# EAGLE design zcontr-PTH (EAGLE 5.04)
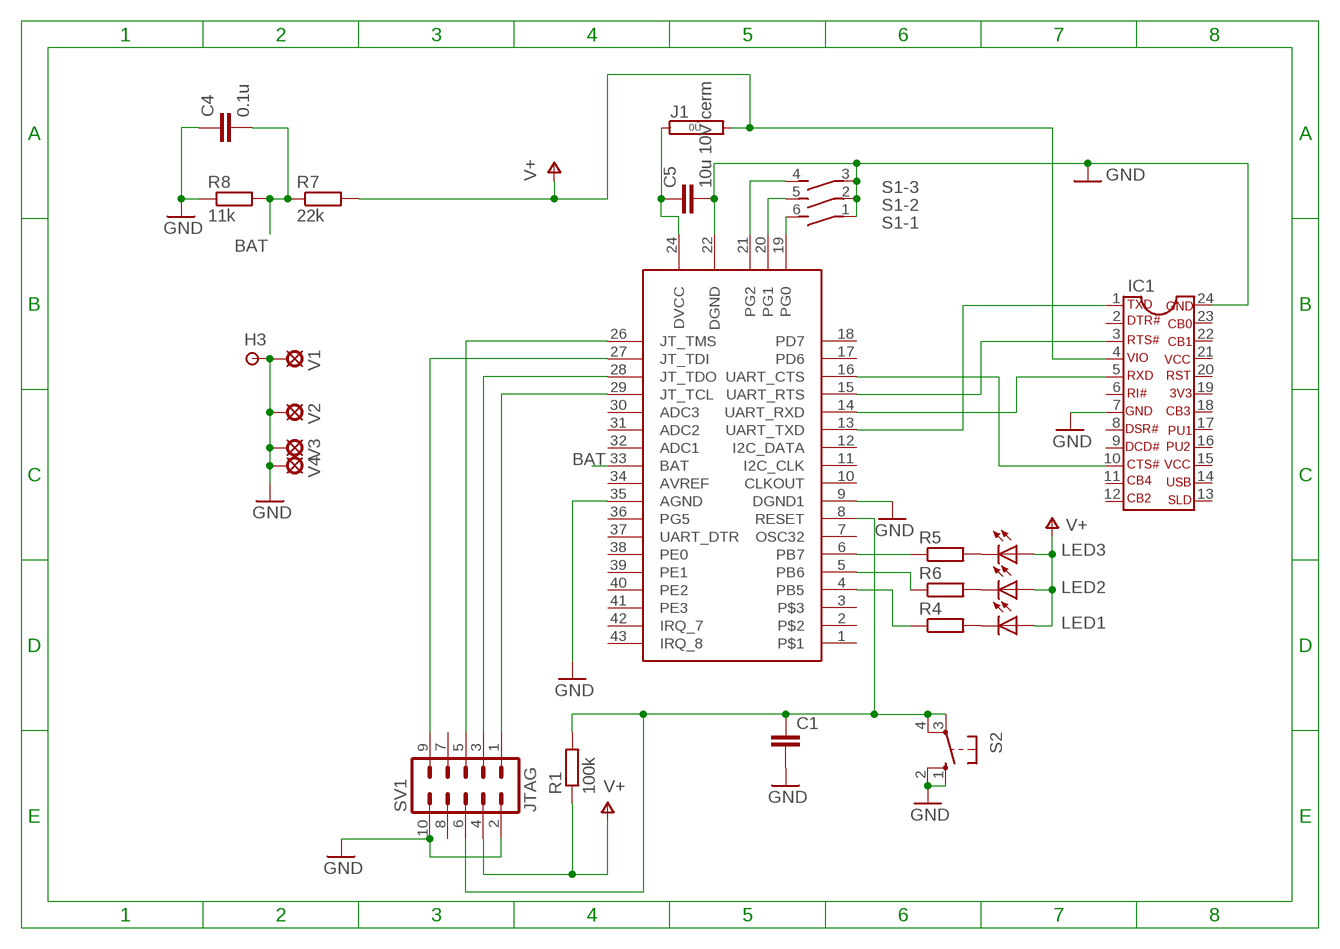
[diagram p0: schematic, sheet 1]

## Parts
C1  C2.5P  [C025-030X050]
C4  0.1u  C5P  [C050-030-075]
C5  10u 10V cerm  CSMT0805  [C0805]
H3  HOLE/SMALL  [1,6/0,8]
IC1  UM232R-6  [DIL24-6]
J1  0R  [0R/10]
LED1  LED-3MM3MM  [HLMP-D105]
LED2  LED-3MM3MM  [HLMP-D105]
LED3  LED-3MM3MM  [HLMP-D105]
R1  100k  R  [0207/10]
R4  470  R  [0207/10]
R5  150  R  [0207/10]
R6  220  R  [0207/10]
R7  22k  R  [0207/10]
R8  11k  R  [0207/10]
S1  DIP-SW-03  [DIP-SW-3]
S2  10-XX  [B3F-10XX]
SV1  JTAG  ML10  [ML10]
U$1  ZDM-A1281-A2N  [ZIGSMD]
V1  HOLE/VIA  [LSP10]
V2  HOLE/VIA  [LSP10]
V3  HOLE/VIA  [LSP10]
V4  HOLE/VIA  [LSP10]

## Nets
BAT: C4.2 R7.1 R8.2 U$1.33(BAT)
GND [supply]: C1.2 C4.1 C5.2 H3.1(P) IC1.7 IC1.24 R8.1 S1.1 S1.2 S1.3 S2.1(S) S2.2(S1) SV1.2 SV1.10 U$1.9(DGND1) U$1.22(DGND) U$1.35(AGND) V1.MP V2.MP V3.MP V4.MP
N$1: S1.6 U$1.19(PG0)
N$2: IC1.10 U$1.16(UART_CTS)
N$3: IC1.3 U$1.15(UART_RTS)
N$4: IC1.5 U$1.14(UART_RXD)
N$5: IC1.1 U$1.13(UART_TXD)
N$6: LED3.K(C) R5.2
N$7: LED2.K(C) R6.2
N$8: LED1.K(C) R4.2
N$9: R5.1 U$1.6(PB7)
N$10: SV1.1 U$1.29(JT_TCL)
N$11: SV1.9 U$1.27(JT_TDI)
N$12: SV1.3 U$1.28(JT_TDO)
N$13: C1.1 R1.2 S2.3(P) S2.4(P1) SV1.6 U$1.8(RESET)
N$14: R6.1 U$1.5(PB6)
N$15: R4.1 U$1.4(PB5)
N$16: S1.5 U$1.20(PG1)
N$17: S1.4 U$1.21(PG2)
N$19: SV1.5 U$1.26(JT_TMS)
N$31 [supply]: C5.1 J1.1 U$1.24(DVCC)
V+: IC1.4 J1.2 LED1.A LED2.A LED3.A R1.1 R7.2 SV1.4
Unconnected: IC1.2 IC1.6 IC1.8 IC1.9 IC1.11 IC1.12 IC1.13 IC1.14 IC1.15 IC1.16 IC1.17 IC1.18 IC1.19 IC1.20 IC1.21 IC1.22 IC1.23 SV1.7 SV1.8 U$1.1 U$1.2 U$1.3 U$1.7(OSC32) U$1.10(CLKOUT) U$1.11(I2C_CLK) U$1.12(I2C_DATA) U$1.17(PD6) U$1.18(PD7) U$1.30(ADC3) U$1.31(ADC2) U$1.32(ADC1) U$1.34(AVREF) U$1.36(PG5) U$1.37(UART_DTR) U$1.38(PE0) U$1.39(PE1) U$1.40(PE2) U$1.41(PE3) U$1.42(IRQ_7) U$1.43(IRQ_8)

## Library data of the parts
C1 C4 C5 = ee2parts:C: Capacitor
H3 = ee2parts:HOLE/SMALL: SMALL THROUGH-HOLE PAD/TESTPOINT
IC1 = ee2parts:UM232R: USB to Serial Module Provides easy USB interface to serial (UART) with power supply
J1 = jumper:0R: Bridge 0R 10mm
LED1-LED3 = ee2parts:LED-3MM: LED
R1 R4-R8 = ee2parts:R: Resistor
S1 = ee2parts:DIP-SW-03: DIL/CODE SWITCH
S2 = switch-omron:10-XX: OMRON SWITCH
SV1 = con-harting-ml:ML10: HARTING
U$1 = 0Zigbit:ZDM-A1281-A2
V1-V4 = ee2parts:HOLE/VIA: FIXED VIA

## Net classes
1 supply: width 0.508 mm

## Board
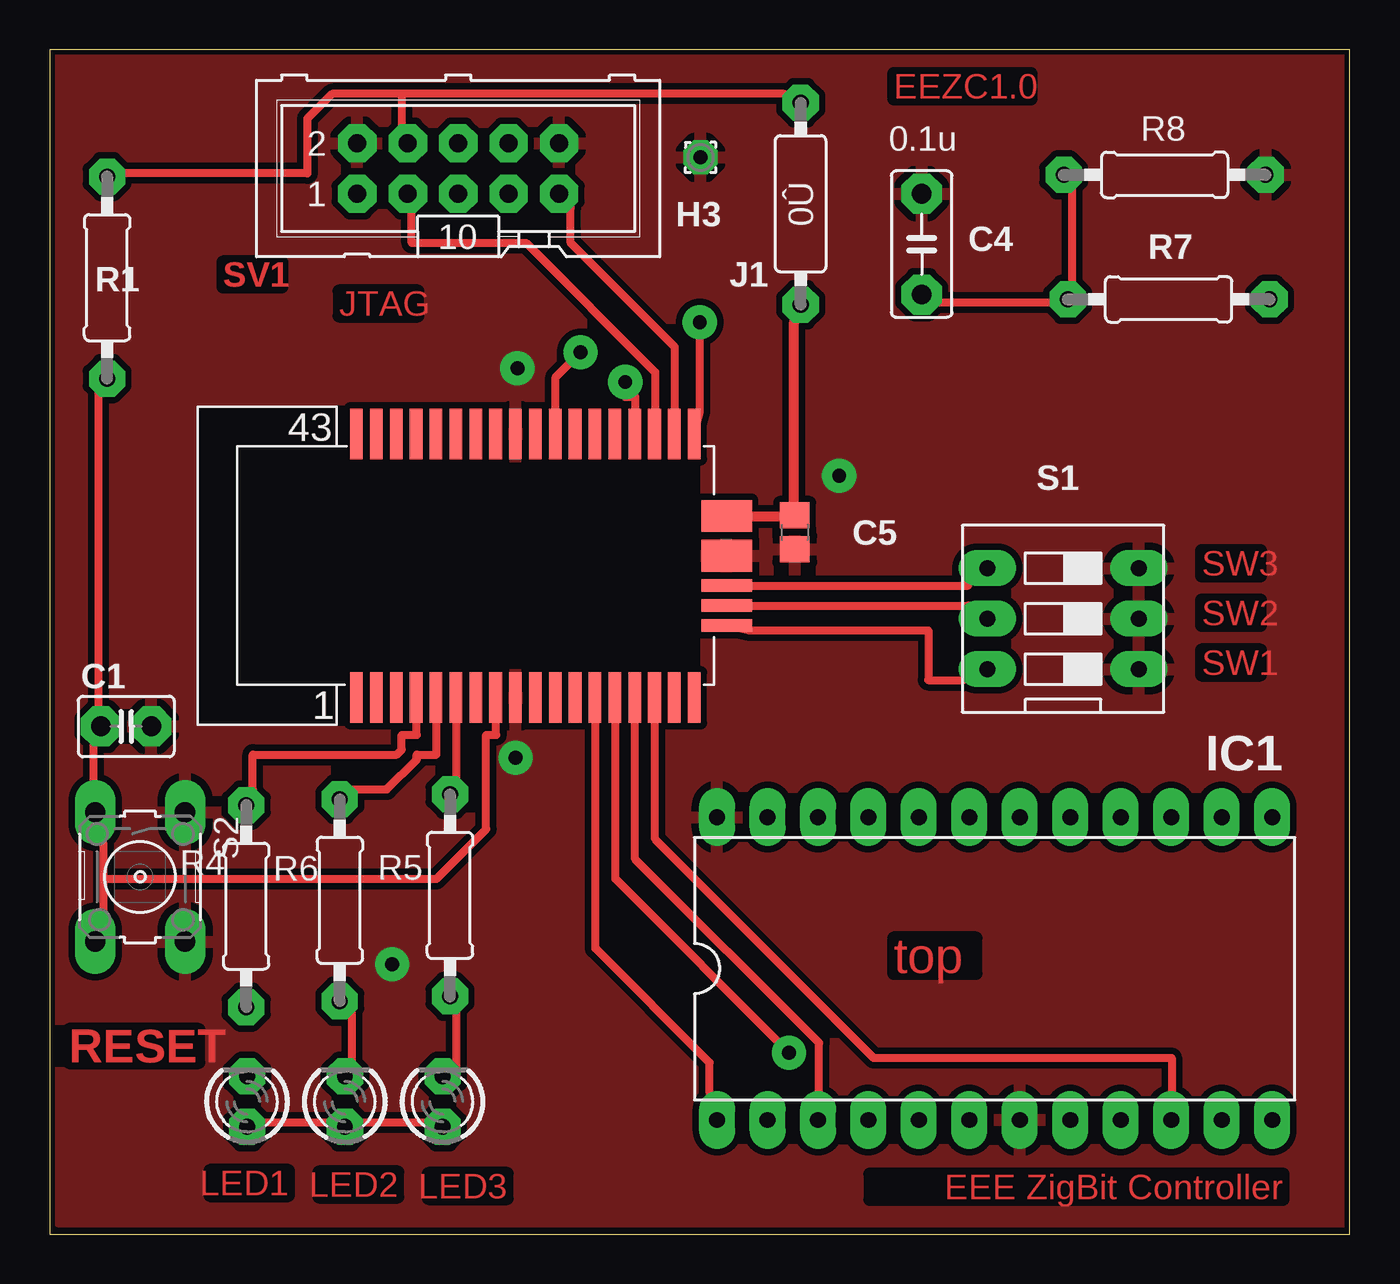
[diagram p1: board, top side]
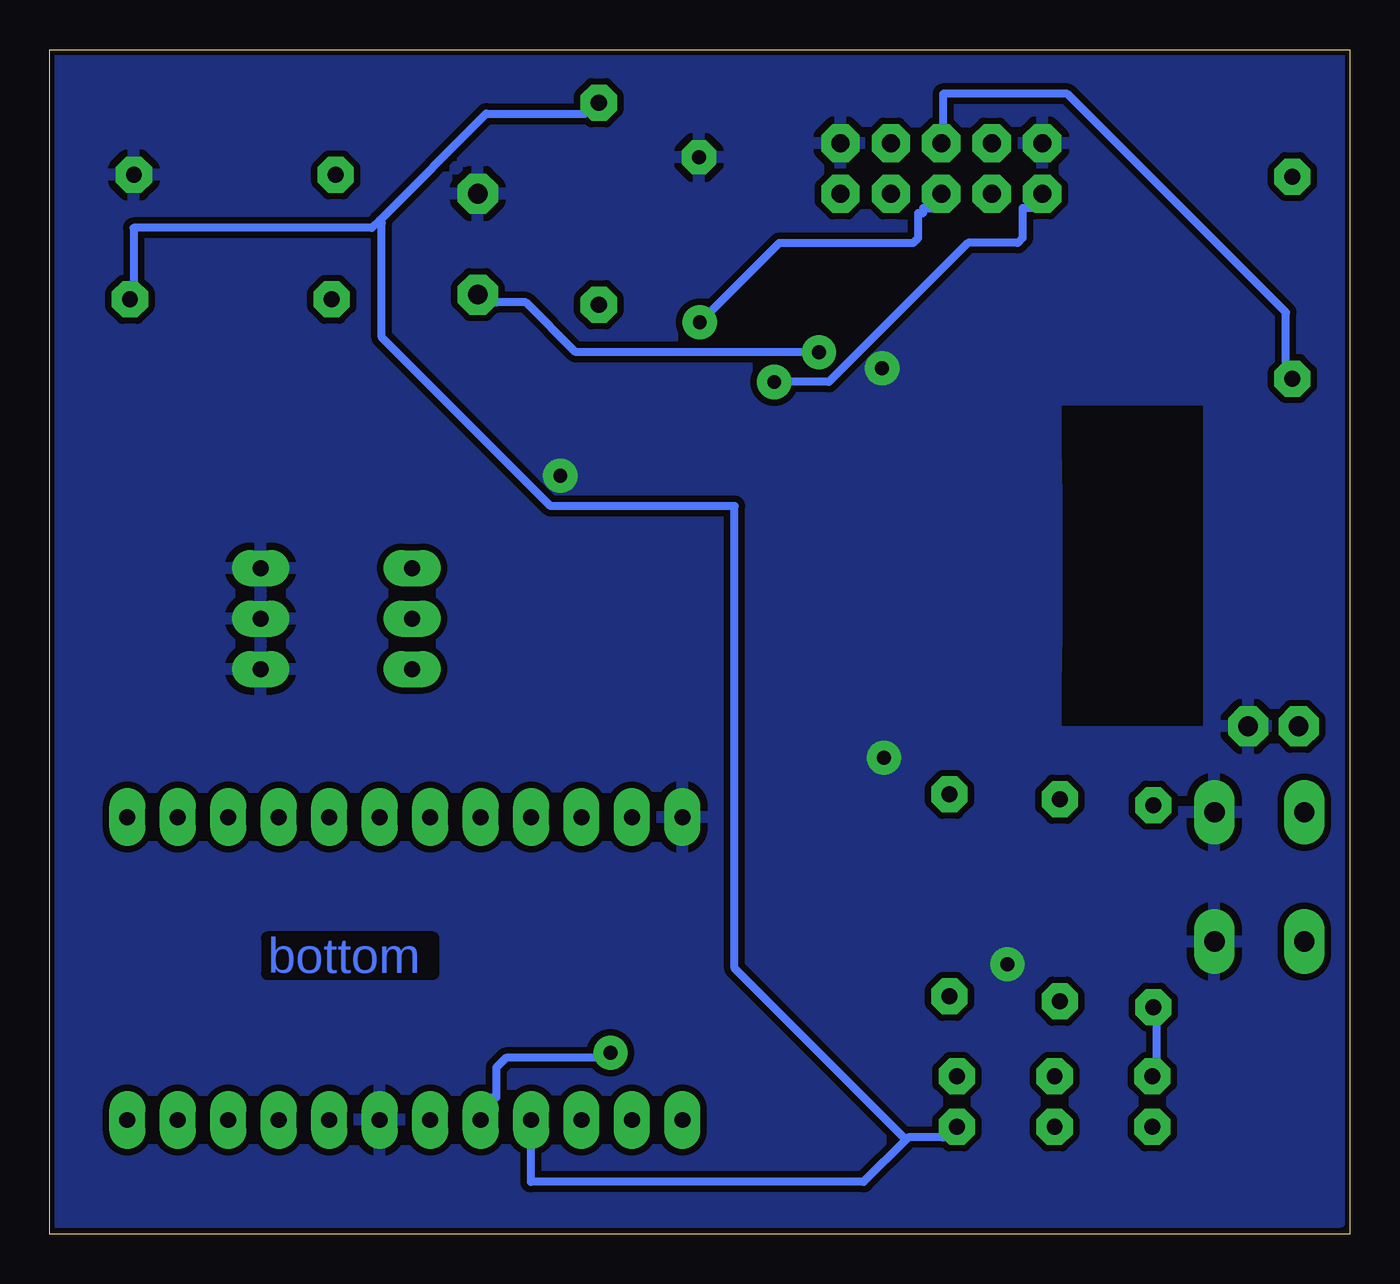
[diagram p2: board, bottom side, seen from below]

Size 65.44 x 59.6 mm. Coordinates in mm from the lower left corner, seen from the top.
Outline: 0,0 65.44,0 65.44,59.6 0,59.6 0,0
Copper layers (1*16): Top 0.035mm / dielectric 1.5mm / Bottom 0.035mm
Design rules "zigbit_rules": minimum track width 16mil, minimum drill 0.7mm, track to track 13mil, track to pad 13mil, pad to pad 13mil, via to via 13mil, smd to smd 0mil, copper to edge 10mil, drill to drill 10mil, minimum pad ring 20mil, minimum via ring 20mil, stop-mask expansion 0mil, vias tented up to drill 0mil, thermal gap 15mil

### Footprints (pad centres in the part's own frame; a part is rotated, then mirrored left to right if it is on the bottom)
C025-030X050 = drill 1 octagon: 1 -1.27,0; 2 1.27,0
C050-030-075 = drill 1 octagon: 1 -2.54,0; 2 2.54,0
C0805 = smd 1.3 x 1.5: 1 -0.85,0; 2 0.85,0
1,6/0,8 = drill 0.7 pad 1.6 octagon: 1 0,0
DIL24-6 = drill 0.8 long: 1 -13.97,-7.62; 2 -11.43,-7.62; 3 -8.89,-7.62; 4 -6.35,-7.62; 5 -3.81,-7.62; 6 -1.27,-7.62; 7 1.27,-7.62; 8 3.81,-7.62; 9 6.35,-7.62; 10 8.89,-7.62; 11 11.43,-7.62; 12 13.97,-7.62; 13 13.97,7.62; 14 11.43,7.62; 15 8.89,7.62; 16 6.35,7.62; 17 3.81,7.62; 18 1.27,7.62; 19 -1.27,7.62; 20 -3.81,7.62; 21 -6.35,7.62; 22 -8.89,7.62; 23 -11.43,7.62; 24 -13.97,7.62
0R/10 = drill 0.813 pad 1.6 octagon: 1 -5.08,0; 2 5.08,0
HLMP-D105 = drill 0.8 octagon: A -1.27,0; K 1.27,0
0207/10 = drill 0.8 octagon: 1 -5.08,0; 2 5.08,0
DIP-SW-3 = drill 0.8 long: 1 -2.54,-3.81; 2 0,-3.81; 3 2.54,-3.81; 4 2.54,3.81; 5 0,3.81; 6 -2.54,3.81
B3F-10XX = drill 1.016 long: 1 -3.251,2.261; 2 3.251,2.261; 3 -3.251,-2.261; 4 3.251,-2.261
ML10 = drill 0.914 octagon: 1 -5.08,-1.27; 2 -5.08,1.27; 3 -2.54,-1.27; 4 -2.54,1.27; 5 0,-1.27; 6 0,1.27; 7 2.54,-1.27; 8 2.54,1.27; 9 5.08,-1.27; 10 5.08,1.27
ZIGSMD = smd 0.635 x 2.54: 1 7,6.635; 2 6,6.635; 3 5,6.635; 4 4,6.635; 5 3,6.635; 6 2,6.635; 7 1,6.635; 8 0,6.635; 9 -1,6.635; 10 -2,6.635; 11 -3,6.635; 12 -4,6.635; 13 -5,6.635; 14 -6,6.635; 15 -7,6.635; 16 -8,6.635; 17 -9,6.635; 18 -10,6.635; 26 -10,-6.635; 27 -9,-6.635; 28 -8,-6.635; 29 -7,-6.635; 30 -6,-6.635; 31 -5,-6.635; 32 -4,-6.635; 33 -3,-6.635; 34 -2,-6.635; 35 -1,-6.635; 36 0,-6.635; 37 1,-6.635; 38 2,-6.635; 39 3,-6.635; 40 4,-6.635; 41 5,-6.635; 42 6,-6.635; 43 7,-6.635 | smd 2.54 x 0.635: 19 -11.635,3; 20 -11.635,2; 21 -11.635,1 | smd 2.54 x 1.6: 22 -11.635,-0.5; 24 -11.635,-2.5
LSP10 = drill 0.7 pad 1.016 round: MP 0,0

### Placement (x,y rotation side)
C1  3.85,25.55 0 top
C4  43.89,49.82 270 top
C5  37.5,35.32 270 top
H3  32.76,54.18 0 top
IC1  47.56,13.37 0 top
J1  37.8,51.85 90 top
LED1  9.94,6.67 90 top
LED2  14.86,6.67 90 top
LED3  19.78,6.67 90 top
R1  2.89,48.13 270 top
R4  9.89,16.51 270 top
R5  20.14,17.05 270 top
R6  14.6,16.8 270 top
R7  56.32,47.04 0 top
R8  56.12,53.3 180 top
S1  51.01,30.97 90 top
S2  4.55,17.98 270 top
SV1  20.56,53.62 0 top
U$1  22.44,33.64 180 top
V1  17.24,13.59 0 top
V2  23.54,43.58 0 top
V3  23.44,23.97 0 top
V4  39.74,38.16 0 top

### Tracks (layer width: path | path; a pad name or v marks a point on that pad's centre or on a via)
BAT  (via drill 0.7)
  Top 0.406: R8.2 51.47,52.63 51.47,47.88 R7.1 50.47,46.88 44.72,46.88 C4.2 | v26.72,44.38 25.47,43.13 25.47,41.38 U$1.33
  Bottom 0.406: v26.72,44.38 38.97,44.38 41.47,46.88 42.97,46.88 C4.2
GND
  pour Bottom: 0.47,59.25 65.28,59.25 65.28,0.63 0.47,0.63
  pour Top: 0.47,59.25 65.28,59.25 65.28,0.63 0.47,0.63
N$1
  Top 0.406: U$1.19 35.22,30.38 44.22,30.38 44.22,27.88 45.97,27.88 S1.6
N$2
  Top 0.406: U$1.16 30.47,25.88 30.47,19.88 41.47,8.88 56.47,8.88 56.47,7.13 IC1.10
N$3
  Top 0.406: U$1.15 29.47,25.88 29.47,18.88 38.72,9.63 38.72,7.13 IC1.3
N$4  (via drill 0.7)
  Top 0.406: v37.22,9.13 28.47,17.88 28.47,25.88 U$1.14
  Bottom 0.406: v37.22,9.13 37.47,8.88 42.47,8.88 42.97,8.38 42.97,6.88 43.22,6.88 IC1.5
N$5
  Top 0.406: U$1.13 27.47,25.88 27.47,14.38 33.22,8.63 33.22,7.13 IC1.1
N$6
  Top 0.406: LED3.K 20.47,8.38 20.47,11.13 R5.2
N$7
  Top 0.406: LED2.K 15.22,8.63 15.22,11.13 R6.2
N$8
  Bottom 0.406: R4.2 9.72,10.63 9.72,8.63 LED1.K
N$9
  Top 0.406: U$1.6 20.47,25.88 20.47,22.88 R5.1
N$10  (via drill 0.7)
  Top 0.406: v28.97,42.88 28.97,42.13 29.47,42.13 29.47,41.38 U$1.29
  Bottom 0.406: v28.97,42.88 26.22,42.88 19.22,49.88 16.72,49.88 16.47,50.13 16.47,51.63 15.97,51.63 SV1.1
N$11
  Top 0.406: U$1.27 31.47,41.38 31.47,44.63 26.22,49.88 26.22,51.63 SV1.9
N$12
  Top 0.406: U$1.28 30.47,41.38 30.47,43.38 23.97,49.88 18.22,49.88 18.22,51.63 SV1.3
N$13
  Top 0.406: 2.72,17.88 19.47,17.88 21.97,20.38 21.97,25.13 22.47,25.13 22.47,25.88 U$1.8 | 2.72,17.88 2.72,19.63 S2.3 2.22,22.63 2.22,24.63 C1.1 2.47,26.38 2.47,42.38 R1.2 | 2.72,17.88 2.72,16.13 S2.4
  Bottom 0.406: SV1.6 20.47,55.63 20.47,57.38 14.22,57.38 3.22,46.38 3.22,43.88 R1.2
N$14
  Top 0.406: U$1.5 19.47,25.88 19.47,24.13 18.47,24.13 18.47,23.88 16.97,22.38 15.22,22.38 R6.1
N$15
  Top 0.406: U$1.4 18.47,25.88 18.47,25.13 17.72,25.13 17.72,24.38 17.47,24.13 10.22,24.13 10.22,22.38 R4.1
N$16
  Top 0.406: U$1.20 35.22,31.63 46.22,31.63 S1.5
N$17
  Top 0.406: U$1.21 35.22,32.63 46.22,32.63 46.22,32.88 S1.4
N$19  (via drill 0.7)
  Top 0.406: v32.72,45.88 32.72,41.38 U$1.26
  Bottom 0.406: v32.72,45.88 28.72,49.88 21.97,49.88 21.72,50.13 21.72,51.38 21.47,51.38 21.47,51.63 20.97,51.63 SV1.5
N$31
  Top 0.508: U$1.24 35.22,36.13 36.97,36.13 C5.1 37.47,36.63 37.47,45.88 J1.1
V+
  Top 0.406: LED1.A 10.72,5.63 13.97,5.63 LED2.A 15.72,5.63 18.97,5.63 LED3.A | 17.72,57.38 14.22,57.38 12.97,56.13 12.97,53.38 3.72,53.38 R1.1 | 17.72,57.38 17.72,55.63 SV1.4 | 17.72,57.38 36.97,57.38 J1.2
  Bottom 0.406: 22.34,4.75 22.22,4.88 20.47,4.88 LED3.A | 22.34,4.75 24.47,2.63 41.22,2.63 41.22,4.38 IC1.4 | 48.84,51.01 43.47,56.38 38.47,56.38 J1.2 | 48.84,51.01 49.22,50.63 61.22,50.63 61.22,47.88 R7.2 | 22.34,4.75 30.97,13.38 30.97,36.63 40.22,36.63 48.72,45.13 48.72,50.88 48.84,51.01

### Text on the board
Top: EEZC1.0 | SW3 | SW2 | SW1 | top | RESET | EEE ZigBit Controller
Bottom: bottom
